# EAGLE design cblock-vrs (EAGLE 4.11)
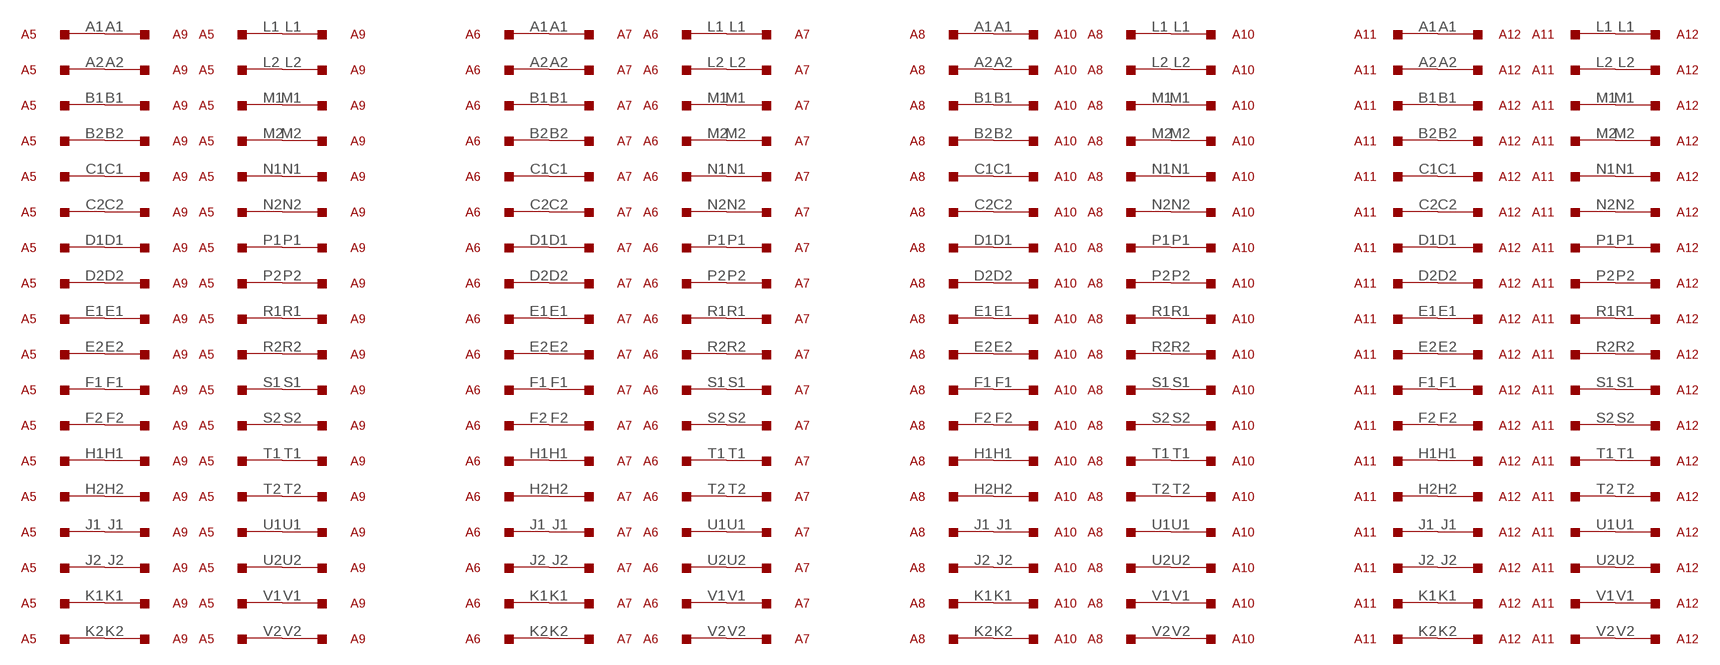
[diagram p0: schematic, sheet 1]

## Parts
A5  M916  [H807]
A6  M916  [H807]
A7  M916  [H807]
A8  M916  [H807]
A9  M916  [H807]
A10  M916  [H807]
A11  M916  [H807]
A12  M916  [H807]

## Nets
N$26: A5.L1 A9.L1
N$33: A5.L2 A9.L2
N$34: A5.M1 A9.M1
N$35: A5.M2 A9.M2
N$36: A5.N1 A9.N1
N$49: A5.N2 A9.N2
N$50: A5.P1 A9.P1
N$51: A5.P2 A9.P2
N$52: A5.R1 A9.R1
N$69: A5.R2 A9.R2
N$70: A5.S1 A9.S1
N$71: A5.S2 A9.S2
N$72: A5.T1 A9.T1
N$73: A5.T2 A9.T2
N$74: A5.U1 A9.U1
N$75: A5.U2 A9.U2
N$76: A5.V1 A9.V1
N$81: A5.V2 A9.V2
N$82: A5.A1 A9.A1
N$83: A5.A2 A9.A2
N$84: A5.B1 A9.B1
N$85: A5.B2 A9.B2
N$86: A5.C1 A9.C1
N$87: A5.C2 A9.C2
N$88: A5.D1 A9.D1
N$89: A5.D2 A9.D2
N$90: A5.E1 A9.E1
N$91: A5.E2 A9.E2
N$92: A5.F1 A9.F1
N$93: A5.F2 A9.F2
N$95: A5.H1 A9.H1
N$96: A5.H2 A9.H2
N$97: A5.J1 A9.J1
N$98: A5.J2 A9.J2
N$99: A5.K1 A9.K1
N$100: A5.K2 A9.K2
N$113: A6.L1 A7.L1
N$114: A6.L2 A7.L2
N$115: A6.M1 A7.M1
N$116: A6.M2 A7.M2
N$117: A6.N1 A7.N1
N$118: A6.N2 A7.N2
N$119: A6.P1 A7.P1
N$120: A6.P2 A7.P2
N$121: A6.R1 A7.R1
N$122: A6.R2 A7.R2
N$123: A6.S1 A7.S1
N$137: A6.S2 A7.S2
N$186: A6.T1 A7.T1
N$187: A6.T2 A7.T2
N$188: A6.U1 A7.U1
N$189: A6.U2 A7.U2
N$190: A6.V1 A7.V1
N$191: A6.V2 A7.V2
N$192: A6.A1 A7.A1
N$193: A6.A2 A7.A2
N$194: A6.B1 A7.B1
N$195: A6.B2 A7.B2
N$196: A6.C1 A7.C1
N$197: A6.C2 A7.C2
N$198: A6.D1 A7.D1
N$199: A6.D2 A7.D2
N$200: A6.E1 A7.E1
N$201: A6.E2 A7.E2
N$202: A6.F1 A7.F1
N$203: A6.F2 A7.F2
N$204: A6.H1 A7.H1
N$205: A6.H2 A7.H2
N$206: A6.J1 A7.J1
N$207: A6.J2 A7.J2
N$208: A6.K1 A7.K1
N$209: A6.K2 A7.K2
N$210: A8.L1 A10.L1
N$211: A8.L2 A10.L2
N$212: A8.M1 A10.M1
N$213: A8.M2 A10.M2
N$214: A8.N1 A10.N1
N$215: A8.N2 A10.N2
N$216: A8.P1 A10.P1
N$217: A8.P2 A10.P2
N$218: A8.R1 A10.R1
N$219: A8.R2 A10.R2
N$220: A8.S1 A10.S1
N$221: A8.S2 A10.S2
N$222: A8.T1 A10.T1
N$223: A8.T2 A10.T2
N$224: A8.U1 A10.U1
N$225: A8.U2 A10.U2
N$226: A8.V1 A10.V1
N$227: A8.V2 A10.V2
N$228: A8.A1 A10.A1
N$229: A8.A2 A10.A2
N$230: A8.B1 A10.B1
N$231: A8.B2 A10.B2
N$232: A8.C1 A10.C1
N$233: A8.C2 A10.C2
N$234: A8.D1 A10.D1
N$235: A8.D2 A10.D2
N$236: A8.E1 A10.E1
N$237: A8.E2 A10.E2
N$238: A8.F1 A10.F1
N$239: A8.F2 A10.F2
N$240: A8.H1 A10.H1
N$241: A8.H2 A10.H2
N$242: A8.J1 A10.J1
N$243: A8.J2 A10.J2
N$244: A8.K1 A10.K1
N$245: A8.K2 A10.K2
N$246: A11.L1 A12.L1
N$247: A11.L2 A12.L2
N$248: A11.M1 A12.M1
N$249: A11.M2 A12.M2
N$250: A11.N1 A12.N1
N$251: A11.N2 A12.N2
N$252: A11.P1 A12.P1
N$253: A11.P2 A12.P2
N$254: A11.R1 A12.R1
N$255: A11.R2 A12.R2
N$256: A11.S1 A12.S1
N$257: A11.S2 A12.S2
N$258: A11.T1 A12.T1
N$259: A11.T2 A12.T2
N$260: A11.U1 A12.U1
N$261: A11.U2 A12.U2
N$262: A11.V1 A12.V1
N$263: A11.V2 A12.V2
N$264: A11.A1 A12.A1
N$265: A11.A2 A12.A2
N$266: A11.B1 A12.B1
N$267: A11.B2 A12.B2
N$268: A11.C1 A12.C1
N$269: A11.C2 A12.C2
N$270: A11.D1 A12.D1
N$271: A11.D2 A12.D2
N$272: A11.E1 A12.E1
N$273: A11.E2 A12.E2
N$274: A11.F1 A12.F1
N$275: A11.F2 A12.F2
N$276: A11.H1 A12.H1
N$277: A11.H2 A12.H2
N$278: A11.J1 A12.J1
N$279: A11.J2 A12.J2
N$280: A11.K1 A12.K1
N$281: A11.K2 A12.K2

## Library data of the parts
A5-A12 = dec-m:M916: Simple 36 pin connector/wire cable

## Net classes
1 Power: width 0.305 mm, drill 0.305 mm

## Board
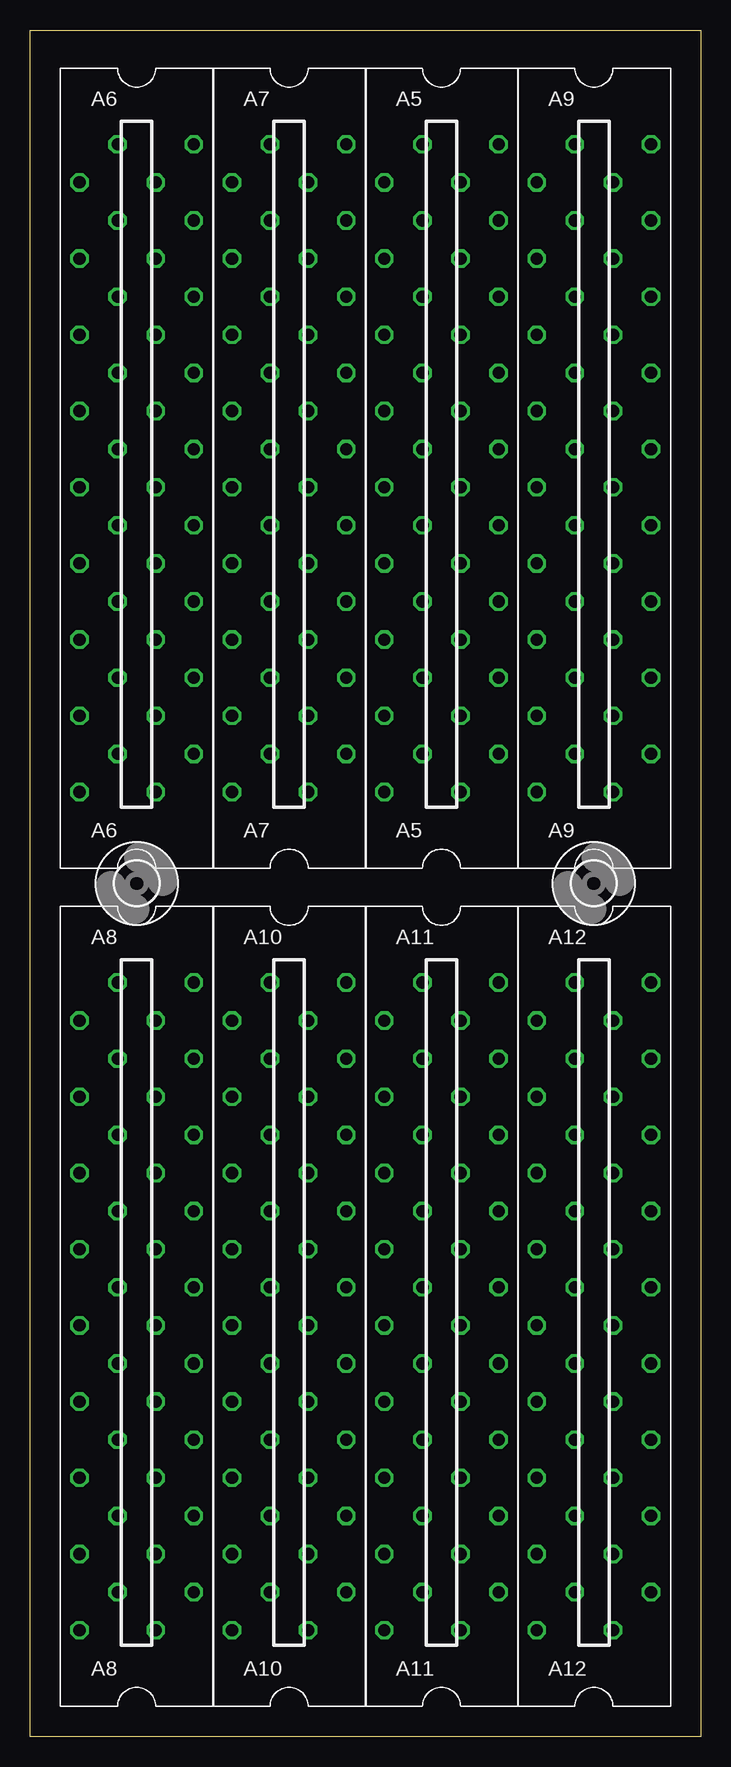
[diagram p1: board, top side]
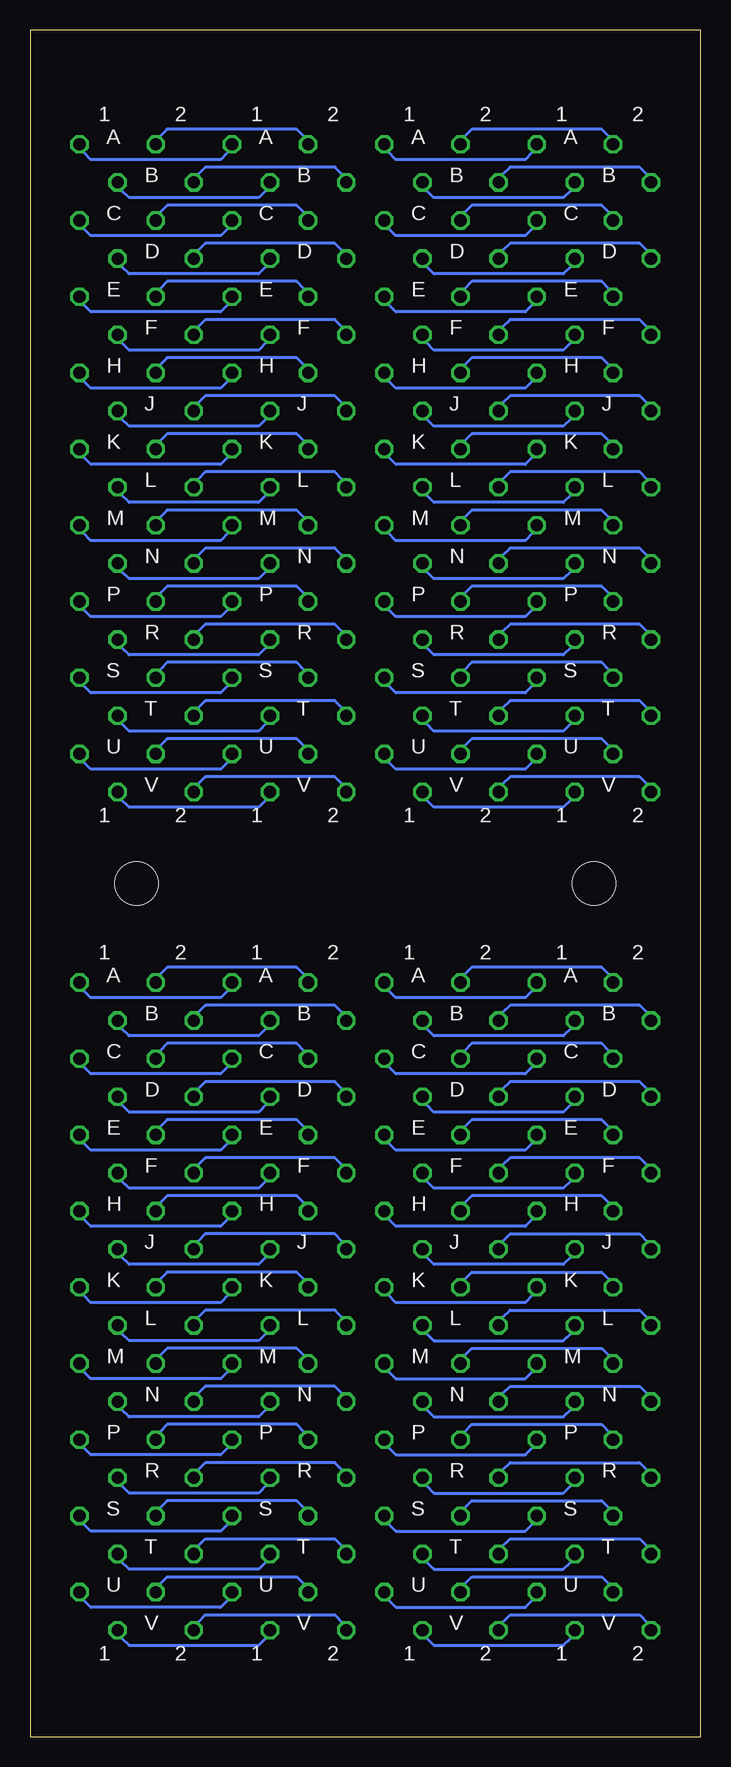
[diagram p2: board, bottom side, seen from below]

Size 55.88 x 142.24 mm. Coordinates in mm from the lower left corner, seen from the top.
Outline: 55.88,0 0,0 0,142.24 55.88,142.24 55.88,0
Copper layers (1*16): Top 0.035mm / dielectric 1.5mm / Bottom 0.035mm
Design rules "olimex10mil": minimum track width 10mil, minimum drill 24mil, track to track 10mil, track to pad 10mil, pad to pad 10mil, via to via 10mil, smd to smd 10mil, copper to edge 40mil, drill to drill 10mil, minimum pad ring 10mil, minimum via ring 8mil, stop-mask expansion 0mil, vias tented up to drill 0mil, thermal gap 10mil

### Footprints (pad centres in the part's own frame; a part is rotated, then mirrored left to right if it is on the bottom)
H807 = drill 1.016 octagon: A1 4.763,28.575; A2 -1.587,28.575; B1 1.587,25.4; B2 -4.763,25.4; C1 4.763,22.225; C2 -1.587,22.225; D1 1.587,19.05; D2 -4.763,19.05; E1 4.763,15.875; E2 -1.587,15.875; F1 1.587,12.7; F2 -4.763,12.7; H1 4.763,9.525; H2 -1.587,9.525; J1 1.587,6.35; J2 -4.763,6.35; K1 4.763,3.175; K2 -1.587,3.175; L1 1.587,0; L2 -4.763,0; M1 4.763,-3.175; M2 -1.587,-3.175; N1 1.587,-6.35; N2 -4.763,-6.35; P1 4.763,-9.525; P2 -1.587,-9.525; R1 1.587,-12.7; R2 -4.763,-12.7; S1 4.763,-15.875; S2 -1.587,-15.875; T1 1.587,-19.05; T2 -4.763,-19.05; U1 4.763,-22.225; U2 -1.587,-22.225; V1 1.587,-25.4; V2 -4.763,-25.4
3,6 = hole 3.6: 0,0

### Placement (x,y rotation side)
A5  34.29,104.14 0 top
A6  8.89,104.14 0 top
A7  21.59,104.14 0 top
A8  8.89,34.29 0 top
A9  46.99,104.14 0 top
A10  21.59,34.29 0 top
A11  34.29,34.29 0 top
A12  46.99,34.29 0 top
U$5  [3,6]  8.89,71.12 0 top
U$6  [3,6]  46.99,71.12 0 top

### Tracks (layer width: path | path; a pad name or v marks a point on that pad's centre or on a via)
N$26
  Bottom 0.254: A5.L1 36.2,103.5 36.83,102.87 47.62,102.87 48.26,103.5 A9.L1
N$33
  Bottom 0.254: A5.L2 29.84,104.78 30.48,105.41 41.27,105.41 41.91,104.78 A9.L2
N$34
  Bottom 0.254: A5.M1 39.37,100.33 40.01,99.69 50.8,99.69 51.44,100.33 A9.M1
N$35
  Bottom 0.254: A5.M2 33.02,101.6 33.66,102.23 44.45,102.23 45.09,101.6 A9.M2
N$36
  Bottom 0.254: A5.N1 36.2,97.16 36.83,96.52 47.62,96.52 48.26,97.16 A9.N1
N$49
  Bottom 0.254: A5.N2 29.84,98.42 30.48,99.06 41.27,99.06 41.91,98.42 A9.N2
N$50
  Bottom 0.254: A5.P1 39.37,93.98 40.01,93.34 50.8,93.34 51.44,93.98 A9.P1
N$51
  Bottom 0.254: A5.P2 33.02,95.25 33.66,95.89 44.45,95.89 45.09,95.25 A9.P2
N$52
  Bottom 0.254: A5.R1 36.2,90.81 36.83,90.17 47.62,90.17 48.26,90.81 A9.R1
N$69
  Bottom 0.254: A5.R2 29.84,92.08 30.48,92.71 41.27,92.71 41.91,92.08 A9.R2
N$70
  Bottom 0.254: A5.S1 39.37,87.63 40.01,87 50.8,87 51.44,87.63 A9.S1
N$71
  Bottom 0.254: A5.S2 33.02,88.9 33.66,89.53 44.45,89.53 45.09,88.9 A9.S2
N$72
  Bottom 0.254: A5.T1 36.2,84.45 36.83,83.82 47.62,83.82 48.26,84.45 A9.T1
N$73
  Bottom 0.254: A5.T2 29.84,85.72 30.48,86.36 41.27,86.36 41.91,85.72 A9.T2
N$74
  Bottom 0.254: A5.U1 39.37,81.28 40.01,80.64 50.8,80.64 51.44,81.28 A9.U1
N$75
  Bottom 0.254: A5.U2 33.02,82.55 33.66,83.19 44.45,83.19 45.09,82.55 A9.U2
N$76
  Bottom 0.254: A5.V1 36.2,78.11 36.83,77.47 47.62,77.47 48.26,78.11 A9.V1
N$81
  Bottom 0.254: A5.V2 29.84,79.38 30.48,80.01 41.27,80.01 41.91,79.38 A9.V2
N$82
  Bottom 0.254: A5.A1 39.37,132.08 40.01,131.44 50.8,131.44 51.44,132.08 A9.A1
N$83
  Bottom 0.254: A5.A2 33.02,133.35 33.66,133.99 44.45,133.99 45.09,133.35 A9.A2
N$84
  Bottom 0.254: A5.B1 36.2,128.91 36.83,128.27 47.62,128.27 48.26,128.91 A9.B1
N$85
  Bottom 0.254: A5.B2 29.84,130.18 30.48,130.81 41.27,130.81 41.91,130.18 A9.B2
N$86
  Bottom 0.254: A5.C1 39.37,125.73 40.01,125.09 50.8,125.09 51.44,125.73 A9.C1
N$87
  Bottom 0.254: A5.C2 33.02,127 33.66,127.64 44.45,127.64 45.09,127 A9.C2
N$88
  Bottom 0.254: A5.D1 36.2,122.56 36.83,121.92 47.62,121.92 48.26,122.56 A9.D1
N$89
  Bottom 0.254: A5.D2 29.84,123.83 30.48,124.46 41.27,124.46 41.91,123.83 A9.D2
N$90
  Bottom 0.254: A5.E1 39.37,119.38 40.01,118.75 50.8,118.75 51.44,119.38 A9.E1
N$91
  Bottom 0.254: A5.E2 33.02,120.65 33.66,121.28 44.45,121.28 45.09,120.65 A9.E2
N$92
  Bottom 0.254: A5.F1 36.2,116.2 36.83,115.57 47.62,115.57 48.26,116.2 A9.F1
N$93
  Bottom 0.254: A5.F2 29.84,117.47 30.48,118.11 41.27,118.11 41.91,117.47 A9.F2
N$95
  Bottom 0.254: A5.H1 39.37,113.03 40.01,112.39 50.8,112.39 51.44,113.03 A9.H1
N$96
  Bottom 0.254: A5.H2 33.02,114.3 33.66,114.94 44.45,114.94 45.09,114.3 A9.H2
N$97
  Bottom 0.254: A5.J1 36.2,109.86 36.83,109.22 47.62,109.22 48.26,109.86 A9.J1
N$98
  Bottom 0.254: A5.J2 29.84,111.12 30.48,111.76 41.27,111.76 41.91,111.12 A9.J2
N$99
  Bottom 0.254: A5.K1 39.37,106.68 40.01,106.05 50.8,106.05 51.44,106.68 A9.K1
N$100
  Bottom 0.254: A5.K2 33.02,107.95 33.66,108.58 44.45,108.58 45.09,107.95 A9.K2
N$113
  Bottom 0.254: A6.L1 10.79,103.5 11.43,102.87 22.23,102.87 22.86,103.5 A7.L1
N$114
  Bottom 0.254: A6.L2 4.45,104.78 5.08,105.41 15.88,105.41 16.51,104.78 A7.L2
N$115
  Bottom 0.254: A6.M1 13.97,100.33 14.61,99.69 25.4,99.69 26.04,100.33 A7.M1
N$116
  Bottom 0.254: A6.M2 7.62,101.6 8.26,102.23 19.05,102.23 19.68,101.6 A7.M2
N$117
  Bottom 0.254: A6.N1 10.79,97.16 11.43,96.52 22.23,96.52 22.86,97.16 A7.N1
N$118
  Bottom 0.254: A6.N2 4.45,98.42 5.08,99.06 15.88,99.06 16.51,98.42 A7.N2
N$119
  Bottom 0.254: A6.P1 13.97,93.98 14.61,93.34 25.4,93.34 26.04,93.98 A7.P1
N$120
  Bottom 0.254: A6.P2 7.62,95.25 8.26,95.89 19.05,95.89 19.68,95.25 A7.P2
N$121
  Bottom 0.254: A6.R1 10.79,90.81 11.43,90.17 22.23,90.17 22.86,90.81 A7.R1
N$122
  Bottom 0.254: A6.R2 4.45,92.08 5.08,92.71 15.88,92.71 16.51,92.08 A7.R2
N$123
  Bottom 0.254: A6.S1 13.97,87.63 14.61,87 25.4,87 26.04,87.63 A7.S1
N$137
  Bottom 0.254: A6.S2 7.62,88.9 8.26,89.53 19.05,89.53 19.68,88.9 A7.S2
N$186
  Bottom 0.254: A6.T1 10.79,84.45 11.43,83.82 22.23,83.82 22.86,84.45 A7.T1
N$187
  Bottom 0.254: A6.T2 4.45,85.72 5.08,86.36 15.88,86.36 16.51,85.72 A7.T2
N$188
  Bottom 0.254: A6.U1 13.97,81.28 14.61,80.64 25.4,80.64 26.04,81.28 A7.U1
N$189
  Bottom 0.254: A6.U2 7.62,82.55 8.26,83.19 19.05,83.19 19.68,82.55 A7.U2
N$190
  Bottom 0.254: A6.V1 10.79,78.11 11.43,77.47 22.23,77.47 22.86,78.11 A7.V1
N$191
  Bottom 0.254: A6.V2 4.45,79.38 5.08,80.01 15.88,80.01 16.51,79.38 A7.V2
N$192
  Bottom 0.254: A6.A1 13.97,132.08 14.61,131.44 25.4,131.44 26.04,132.08 A7.A1
N$193
  Bottom 0.254: A6.A2 7.62,133.35 8.26,133.99 19.05,133.99 19.68,133.35 A7.A2
N$194
  Bottom 0.254: A6.B1 10.79,128.91 11.43,128.27 22.23,128.27 22.86,128.91 A7.B1
N$195
  Bottom 0.254: A6.B2 4.45,130.18 5.08,130.81 15.88,130.81 16.51,130.18 A7.B2
N$196
  Bottom 0.254: A6.C1 13.97,125.73 14.61,125.09 25.4,125.09 26.04,125.73 A7.C1
N$197
  Bottom 0.254: A6.C2 7.62,127 8.26,127.64 19.05,127.64 19.68,127 A7.C2
N$198
  Bottom 0.254: A6.D1 10.79,122.56 11.43,121.92 22.23,121.92 22.86,122.56 A7.D1
N$199
  Bottom 0.254: A6.D2 4.45,123.83 5.08,124.46 15.88,124.46 16.51,123.83 A7.D2
N$200
  Bottom 0.254: A6.E1 13.97,119.38 14.61,118.75 25.4,118.75 26.04,119.38 A7.E1
N$201
  Bottom 0.254: A6.E2 7.62,120.65 8.26,121.28 19.05,121.28 19.68,120.65 A7.E2
N$202
  Bottom 0.254: A6.F1 10.79,116.2 11.43,115.57 22.23,115.57 22.86,116.2 A7.F1
N$203
  Bottom 0.254: A6.F2 4.45,117.47 5.08,118.11 15.88,118.11 16.51,117.47 A7.F2
N$204
  Bottom 0.254: A6.H1 13.97,113.03 14.61,112.39 25.4,112.39 26.04,113.03 A7.H1
N$205
  Bottom 0.254: A6.H2 7.62,114.3 8.26,114.94 19.05,114.94 19.68,114.3 A7.H2
N$206
  Bottom 0.254: A6.J1 10.79,109.86 11.43,109.22 22.23,109.22 22.86,109.86 A7.J1
N$207
  Bottom 0.254: A6.J2 4.45,111.12 5.08,111.76 15.88,111.76 16.51,111.12 A7.J2
N$208
  Bottom 0.254: A6.K1 13.97,106.68 14.61,106.05 25.4,106.05 26.04,106.68 A7.K1
N$209
  Bottom 0.254: A6.K2 7.62,107.95 8.26,108.58 19.05,108.58 19.68,107.95 A7.K2
N$210
  Bottom 0.254: A8.L1 10.79,33.66 11.43,33.02 22.23,33.02 22.86,33.66 A10.L1
N$211
  Bottom 0.254: A8.L2 4.45,34.92 5.08,35.56 15.88,35.56 16.51,34.92 A10.L2
N$212
  Bottom 0.254: A8.M1 13.97,30.48 14.61,29.84 25.4,29.84 26.04,30.48 A10.M1
N$213
  Bottom 0.254: A8.M2 7.62,31.75 8.26,32.38 19.05,32.38 19.68,31.75 A10.M2
N$214
  Bottom 0.254: A8.N1 10.79,27.3 11.43,26.67 22.23,26.67 22.86,27.3 A10.N1
N$215
  Bottom 0.254: A8.N2 4.45,28.57 5.08,29.21 15.88,29.21 16.51,28.57 A10.N2
N$216
  Bottom 0.254: A8.P1 13.97,24.13 14.61,23.5 25.4,23.5 26.04,24.13 A10.P1
N$217
  Bottom 0.254: A8.P2 7.62,25.4 8.26,26.04 19.05,26.04 19.68,25.4 A10.P2
N$218
  Bottom 0.254: A8.R1 10.79,20.95 11.43,20.32 22.23,20.32 22.86,20.95 A10.R1
N$219
  Bottom 0.254: A8.R2 4.45,22.23 5.08,22.86 15.88,22.86 16.51,22.23 A10.R2
N$220
  Bottom 0.254: A8.S1 13.97,17.78 14.61,17.14 25.4,17.14 26.04,17.78 A10.S1
N$221
  Bottom 0.254: A8.S2 7.62,19.05 8.26,19.68 19.05,19.68 19.68,19.05 A10.S2
N$222
  Bottom 0.254: A8.T1 10.79,14.61 11.43,13.97 22.23,13.97 22.86,14.61 A10.T1
N$223
  Bottom 0.254: A8.T2 4.45,15.88 5.08,16.51 15.88,16.51 16.51,15.88 A10.T2
N$224
  Bottom 0.254: A8.U1 13.97,11.43 14.61,10.79 25.4,10.79 26.04,11.43 A10.U1
N$225
  Bottom 0.254: A8.U2 7.62,12.7 8.26,13.34 19.05,13.34 19.68,12.7 A10.U2
N$226
  Bottom 0.254: A8.V1 10.79,8.26 11.43,7.62 22.23,7.62 22.86,8.26 A10.V1
N$227
  Bottom 0.254: A8.V2 4.45,9.53 5.08,10.16 15.88,10.16 16.51,9.53 A10.V2
N$228
  Bottom 0.254: A8.A1 13.97,62.23 14.61,61.59 25.4,61.59 26.04,62.23 A10.A1
N$229
  Bottom 0.254: A8.A2 7.62,63.5 8.26,64.14 19.05,64.14 19.68,63.5 A10.A2
N$230
  Bottom 0.254: A8.B1 10.79,59.05 11.43,58.42 22.23,58.42 22.86,59.05 A10.B1
N$231
  Bottom 0.254: A8.B2 4.45,60.33 5.08,60.96 15.88,60.96 16.51,60.33 A10.B2
N$232
  Bottom 0.254: A8.C1 13.97,55.88 14.61,55.24 25.4,55.24 26.04,55.88 A10.C1
N$233
  Bottom 0.254: A8.C2 7.62,57.15 8.26,57.78 19.05,57.78 19.68,57.15 A10.C2
N$234
  Bottom 0.254: A8.D1 10.79,52.7 11.43,52.07 22.23,52.07 22.86,52.7 A10.D1
N$235
  Bottom 0.254: A8.D2 4.45,53.98 5.08,54.61 15.88,54.61 16.51,53.98 A10.D2
N$236
  Bottom 0.254: A8.E1 13.97,49.53 14.61,48.9 25.4,48.9 26.04,49.53 A10.E1
N$237
  Bottom 0.254: A8.E2 7.62,50.8 8.26,51.44 19.05,51.44 19.68,50.8 A10.E2
N$238
  Bottom 0.254: A8.F1 10.79,46.35 11.43,45.72 22.23,45.72 22.86,46.35 A10.F1
N$239
  Bottom 0.254: A8.F2 4.45,47.62 5.08,48.26 15.88,48.26 16.51,47.62 A10.F2
N$240
  Bottom 0.254: A8.H1 13.97,43.18 14.61,42.55 25.4,42.55 26.04,43.18 A10.H1
N$241
  Bottom 0.254: A8.H2 7.62,44.45 8.26,45.09 19.05,45.09 19.68,44.45 A10.H2
N$242
  Bottom 0.254: A8.J1 10.79,40.01 11.43,39.37 22.23,39.37 22.86,40.01 A10.J1
N$243
  Bottom 0.254: A8.J2 4.45,41.27 5.08,41.91 15.88,41.91 16.51,41.27 A10.J2
N$244
  Bottom 0.254: A8.K1 13.97,36.83 14.61,36.2 25.4,36.2 26.04,36.83 A10.K1
N$245
  Bottom 0.254: A8.K2 7.62,38.1 8.26,38.73 19.05,38.73 19.68,38.1 A10.K2
N$246
  Bottom 0.254: A11.L1 36.2,33.66 36.83,33.02 47.62,33.02 48.26,33.66 A12.L1
N$247
  Bottom 0.254: A11.L2 29.84,34.92 30.48,35.56 41.27,35.56 41.91,34.92 A12.L2
N$248
  Bottom 0.254: A11.M1 39.37,30.48 40.01,29.84 50.8,29.84 51.44,30.48 A12.M1
N$249
  Bottom 0.254: A11.M2 33.02,31.75 33.66,32.38 44.45,32.38 45.09,31.75 A12.M2
N$250
  Bottom 0.254: A11.N1 36.2,27.3 36.83,26.67 47.62,26.67 48.26,27.3 A12.N1
N$251
  Bottom 0.254: A11.N2 29.84,28.57 30.48,29.21 41.27,29.21 41.91,28.57 A12.N2
N$252
  Bottom 0.254: A11.P1 39.37,24.13 40.01,23.5 50.8,23.5 51.44,24.13 A12.P1
N$253
  Bottom 0.254: A11.P2 33.02,25.4 33.66,26.04 44.45,26.04 45.09,25.4 A12.P2
N$254
  Bottom 0.254: A11.R1 36.2,20.95 36.83,20.32 47.62,20.32 48.26,20.95 A12.R1
N$255
  Bottom 0.254: A11.R2 29.84,22.23 30.48,22.86 41.27,22.86 41.91,22.23 A12.R2
N$256
  Bottom 0.254: A11.S1 39.37,17.78 40.01,17.14 50.8,17.14 51.44,17.78 A12.S1
N$257
  Bottom 0.254: A11.S2 33.02,19.05 33.66,19.68 44.45,19.68 45.09,19.05 A12.S2
N$258
  Bottom 0.254: A11.T1 36.2,14.61 36.83,13.97 47.62,13.97 48.26,14.61 A12.T1
N$259
  Bottom 0.254: A11.T2 29.84,15.88 30.48,16.51 41.27,16.51 41.91,15.88 A12.T2
N$260
  Bottom 0.254: A11.U1 39.37,11.43 40.01,10.79 50.8,10.79 51.44,11.43 A12.U1
N$261
  Bottom 0.254: A11.U2 33.02,12.7 33.66,13.34 44.45,13.34 45.09,12.7 A12.U2
N$262
  Bottom 0.254: A11.V1 36.2,8.26 36.83,7.62 47.62,7.62 48.26,8.26 A12.V1
N$263
  Bottom 0.254: A11.V2 29.84,9.53 30.48,10.16 41.27,10.16 41.91,9.53 A12.V2
N$264
  Bottom 0.254: A11.A1 39.37,62.23 40.01,61.59 50.8,61.59 51.44,62.23 A12.A1
N$265
  Bottom 0.254: A11.A2 33.02,63.5 33.66,64.14 44.45,64.14 45.09,63.5 A12.A2
N$266
  Bottom 0.254: A11.B1 36.2,59.05 36.83,58.42 47.62,58.42 48.26,59.05 A12.B1
N$267
  Bottom 0.254: A11.B2 29.84,60.33 30.48,60.96 41.27,60.96 41.91,60.33 A12.B2
N$268
  Bottom 0.254: A11.C1 39.37,55.88 40.01,55.24 50.8,55.24 51.44,55.88 A12.C1
N$269
  Bottom 0.254: A11.C2 33.02,57.15 33.66,57.78 44.45,57.78 45.09,57.15 A12.C2
N$270
  Bottom 0.254: A11.D1 36.2,52.7 36.83,52.07 47.62,52.07 48.26,52.7 A12.D1
N$271
  Bottom 0.254: A11.D2 29.84,53.98 30.48,54.61 41.27,54.61 41.91,53.98 A12.D2
N$272
  Bottom 0.254: A11.E1 39.37,49.53 40.01,48.9 50.8,48.9 51.44,49.53 A12.E1
N$273
  Bottom 0.254: A11.E2 33.02,50.8 33.66,51.44 44.45,51.44 45.09,50.8 A12.E2
N$274
  Bottom 0.254: A11.F1 36.2,46.35 36.83,45.72 47.62,45.72 48.26,46.35 A12.F1
N$275
  Bottom 0.254: A11.F2 29.84,47.62 30.48,48.26 41.27,48.26 41.91,47.62 A12.F2
N$276
  Bottom 0.254: A11.H1 39.37,43.18 40.01,42.55 50.8,42.55 51.44,43.18 A12.H1
N$277
  Bottom 0.254: A11.H2 33.02,44.45 33.66,45.09 44.45,45.09 45.09,44.45 A12.H2
N$278
  Bottom 0.254: A11.J1 36.2,40.01 36.83,39.37 47.62,39.37 48.26,40.01 A12.J1
N$279
  Bottom 0.254: A11.J2 29.84,41.27 30.48,41.91 41.27,41.91 41.91,41.27 A12.J2
N$280
  Bottom 0.254: A11.K1 39.37,36.83 40.01,36.2 50.8,36.2 51.44,36.83 A12.K1
N$281
  Bottom 0.254: A11.K2 33.02,38.1 33.66,38.73 44.45,38.73 45.09,38.1 A12.K2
